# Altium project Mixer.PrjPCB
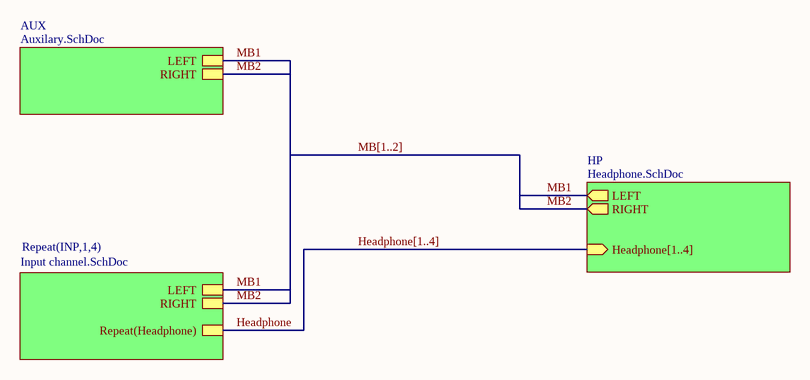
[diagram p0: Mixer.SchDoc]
4 sheets, 97 parts. Net scope: hierarchical (ports join the sheet entries above them; power ports are global).
Board file: Mixer.PCBDOC
Sheets:
  Mixer.SchDoc
    AUX = Auxilary.SchDoc
    HP = Headphone.SchDoc
    INP1 = Input channel.SchDoc
    INP2 = Input channel.SchDoc
    INP3 = Input channel.SchDoc
    INP4 = Input channel.SchDoc

## Sheet Mixer.SchDoc: Multi-Channel Design
size 431 x 279 mm; Organization: Altium Limited; Address1: L3, 12a Rodborough Rd; Address2: Frenchs Forest; Address3: NSW; Address4: Australia 2086; DocumentNumber: 5; SheetNumber: 5; SheetTotal: 8

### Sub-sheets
AUX = Auxilary.SchDoc: LEFT, RIGHT
HP = Headphone.SchDoc: Headphone[1..4] (in), LEFT (out), RIGHT (out)
Repeat(INP,1,4) = Input channel.SchDoc: LEFT, RIGHT, Repeat(Headphone)

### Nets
MB1: sheet AUX/LEFT, sheet HP/LEFT, sheet Repeat(INP,1,4)/LEFT  [project net LCHANNEL]
MB2: sheet AUX/RIGHT, sheet HP/RIGHT, sheet Repeat(INP,1,4)/RIGHT

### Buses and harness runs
bus Headphone[1..4] = sheet HP/Headphone[1..4]
bus MB[1..2]

## Sheet Auxilary.SchDoc: Multi-Channel Design
size 431 x 279 mm; Organization: Altium Limited; Address1: L3, 12a Rodborough Rd; Address2: Frenchs Forest; Address3: NSW; Address4: Australia 2086; DocumentNumber: 1; SheetNumber: 1; SheetTotal: 8
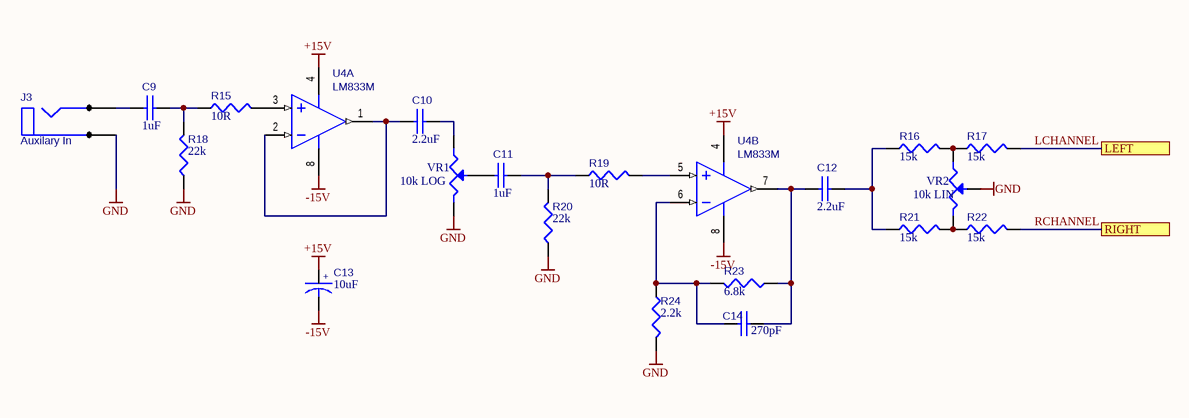
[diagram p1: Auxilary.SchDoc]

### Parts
C9  1uF  [RB.2/.4-NP]
C10  2.2uF  [RB.2/.4-NP]
C11  1uF  [RB.2/.4-NP]
C12  2.2uF  [RB.2/.4-NP]
C13  10uF  [RB.2/.4]
C14  270pF  [RAD0.2]
J3  Auxilary In  [JACK-6.25MM]
R15  10R  [AXIAL0.4]
R16  15k  [AXIAL0.4]
R17  15k  [AXIAL0.4]
R18  22k  [AXIAL0.4]
R19  10R  [AXIAL0.4]
R20  22k  [AXIAL0.4]
R21  15k  [AXIAL0.4]
R22  15k  [AXIAL0.4]
R23  6.8k  [AXIAL0.4]
R24  2.2k  [AXIAL0.4]
U4  LM833M  [DIP8]  (parts A,B of 2)
VR1  10k LOG  [POT - 24MM]
VR2  10k LIN  [POT - 24MM]

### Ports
LEFT, RIGHT

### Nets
+15V: C13.1 U4.4(V-)
-15V: C13.2 U4.8(V+)
GND: J3.3(C) R18.1 R20.1 R24.2 VR1.3 VR2.2(W)
LCHANNEL: R17.2 ; port LEFT
RCHANNEL: R22.2 ; port RIGHT  [project net MB2]
NetC9_1: C9.1 J3.1(A)
NetC9_2: C9.2 R15.1 R18.2
NetC10_1: C10.1 U4.1(OUT1) U4.2(IN1-)
NetC10_2: C10.2 VR1.1
NetC11_1: C11.1 VR1.2(W)
NetC11_2: C11.2 R19.1 R20.2
NetC12_1: C12.1 C14.2 R23.1 U4.7(OUT2)
NetC12_2: C12.2 R16.1 R21.1
NetC14_1: C14.1 R23.2 R24.1 U4.6(IN2-)
NetR15_2: R15.2 U4.3(IN1+)
NetR16_2: R16.2 R17.1 VR2.1
NetR19_2: R19.2 U4.5(IN2+)
NetR21_2: R21.2 R22.1 VR2.3

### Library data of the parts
C9-C12 C14 = CAP: Capacitor
C13 = CAPACITOR POL: Bi-Polar Capacitor
J3 = PHONEJACK MONO
R15-R24 = RES1: Resistor
U4 = LM833M: Fast Settling Dual Operational Amplifier
VR1 VR2 = POT1: Potentiometer

## Sheet Headphone.SchDoc: Multi-Channel Design
size 431 x 279 mm; Organization: Altium Limited; Address1: L3, 12a Rodborough Rd; Address2: Frenchs Forest; Address3: NSW; Address4: Australia 2086; DocumentNumber: 3; SheetNumber: 3; SheetTotal: 8
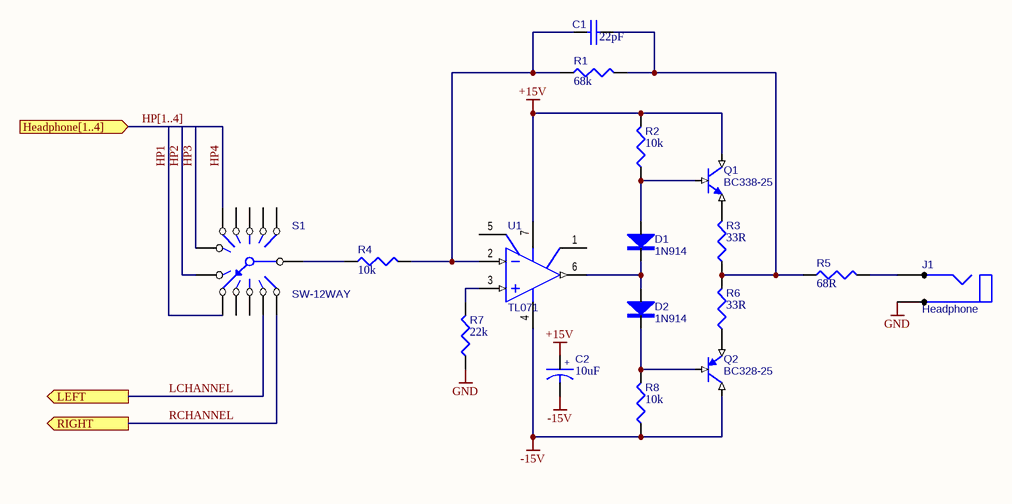
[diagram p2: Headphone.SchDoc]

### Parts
C1  22pF  [RAD0.2]
C2  10uF  [RB.2/.4]
D1  1N914  [DIODE0.4]
D2  1N914  [DIODE0.4]
J1  Headphone  [JACK-6.25MM]
Q1  BC338-25  [TO-92A]
Q2  BC328-25  [TO-92A]
R1  68k  [AXIAL0.4]
R2  10k  [AXIAL0.4]
R3  33R  [AXIAL0.4]
R4  10k  [AXIAL0.4]
R5  68R  [AXIAL0.4]
R6  33R  [AXIAL0.4]
R7  22k  [AXIAL0.4]
R8  10k  [AXIAL0.4]
S1  SW-12WAY  [SW-12WAY]
U1  TL071  [DIP8]

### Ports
Headphone[1..4] (in), LEFT (out), RIGHT (out)

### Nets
+15V: C2.1 Q1.1(C) R2.2 U1.7(VCC+)
-15V: C2.2 Q2.1(C) R8.1 U1.4(VCC-)
GND: J1.3(C) R7.1
HP1: S1.8  [project net Headphone1]
HP2: S1.7  [project net Headphone2]
HP3: S1.6  [project net Headphone3]
HP4: S1.5  [project net Headphone4]
LCHANNEL: S1.11 ; port LEFT
RCHANNEL: S1.12 ; port RIGHT  [project net MB2]
NetC1_1: C1.1 R1.1 R4.2 U1.2(IN-)
NetC1_2: C1.2 R1.2 R3.1 R5.1 R6.2
NetD1_1: D1.1(A) Q1.2(B) R2.1
NetD1_2: D1.2(K) D2.1(A) U1.6(OUT)
NetD2_2: D2.2(K) Q2.2(B) R8.2
NetJ1_1: J1.1(A) R5.2
NetQ1_3: Q1.3(E) R3.2
NetQ2_3: Q2.3(E) R6.1
NetR4_1: R4.1 S1.13
NetR7_2: R7.2 U1.3(IN+)

Not connected (* = marked no-connect by the designer): S1 1 2 3 4 9 10; U1 1(N1/O.S.) 5(O.S._N2)

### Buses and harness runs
bus HP[1..4] = port Headphone[1..4]

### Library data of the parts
C1 = CAP: Capacitor
C2 = CAPACITOR POL: Bi-Polar Capacitor
D1 D2 = 1N914: Diode
J1 = PHONEJACK MONO
Q1 = BC338-25: NPN BJT
Q2 = BC328-25: PNP BJT
R1-R8 = RES1: Resistor
U1 = TL071: Low-Noise  JFET-Input Operational Amplifiers

## Sheet Input channel.SchDoc: Multi-Channel Design
size 431 x 279 mm; Organization: Altium Limited; Address1: L3, 12a Rodborough Rd; Address2: Frenchs Forest; Address3: NSW; Address4: Australia 2086; DocumentNumber: 4; SheetNumber: 4; SheetTotal: 8
Used 4 times, as channels INP1, INP2, INP3, INP4. Parts and nets are listed once, with the designators drawn on the sheet.
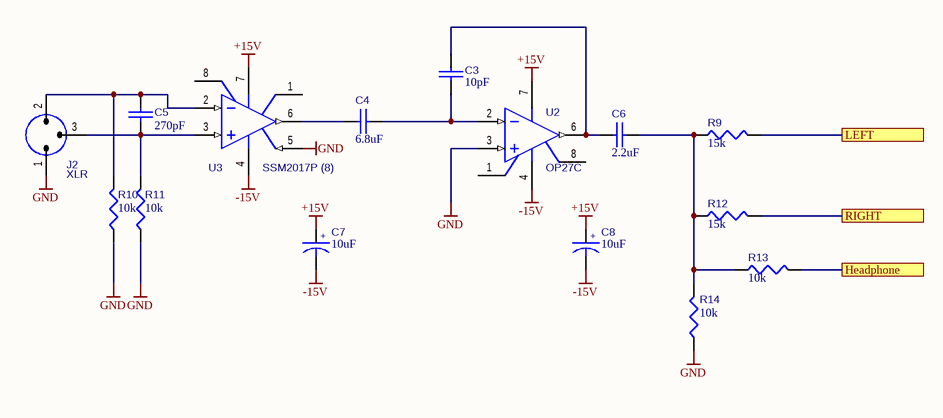
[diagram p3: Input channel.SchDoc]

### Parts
C3  10pF  [RAD0.2]
C4  6.8uF  [RB.2/.4-NP]
C5  270pF  [RAD0.2]
C6  2.2uF  [RB.2/.4-NP]
C7  10uF  [RB.2/.4]
C8  10uF  [RB.2/.4]
J2  XLR  [XLR-FEMALE]
R9  15k  [AXIAL0.4]
R10  10k  [AXIAL0.4]
R11  10k  [AXIAL0.4]
R12  15k  [AXIAL0.4]
R13  10k  [AXIAL0.4]
R14  10k  [AXIAL0.4]
U2  OP27C  [DIP8]
U3  SSM2017P (8)  [DIP8]

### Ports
Headphone, LEFT, RIGHT

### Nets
+15V: C7.1 C8.1 U2.7(V+) U3.7(V+)
-15V: C7.2 C8.2 U2.4(V-) U3.4(V-)
GND: J2.1 R10.1 R11.1 R14.1 U2.3(+IN) U3.5(REF)
Headphone: R13.2 ; port Headphone
LEFT: R9.2 ; port LEFT
RIGHT: R12.2 ; port RIGHT
NetC3_1: C3.1 C4.2 U2.2(-IN)
NetC3_2: C3.2 C6.1 U2.6(OUT)
NetC4_1: C4.1 U3.6(OUT)
NetC5_1: C5.1 J2.2 R10.2 U3.2(IN-)
NetC5_2: C5.2 J2.3 R11.2 U3.3(IN+)
NetC6_2: C6.2 R9.1 R12.1 R13.1 R14.2

Not connected (* = marked no-connect by the designer): U2 1(TRIM) 8(TRIM); U3 1(RG1) 8(RG2)

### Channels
INP1: designators C3=INP1_C3 C4=INP1_C4 C5=INP1_C5 C6=INP1_C6 C7=INP1_C7 C8=INP1_C8 J2=INP1_J2 R9=INP1_R9 R10=INP1_R10 R11=INP1_R11 R12=INP1_R12 R13=INP1_R13 R14=INP1_R14 U2=INP1_U2 U3=INP1_U3; ports Headphone=Headphone1 LEFT=LCHANNEL RIGHT=MB2
INP2: designators C3=INP2_C3 C4=INP2_C4 C5=INP2_C5 C6=INP2_C6 C7=INP2_C7 C8=INP2_C8 J2=INP2_J2 R9=INP2_R9 R10=INP2_R10 R11=INP2_R11 R12=INP2_R12 R13=INP2_R13 R14=INP2_R14 U2=INP2_U2 U3=INP2_U3; ports Headphone=Headphone2 LEFT=LCHANNEL RIGHT=MB2
INP3: designators C3=INP3_C3 C4=INP3_C4 C5=INP3_C5 C6=INP3_C6 C7=INP3_C7 C8=INP3_C8 J2=INP3_J2 R9=INP3_R9 R10=INP3_R10 R11=INP3_R11 R12=INP3_R12 R13=INP3_R13 R14=INP3_R14 U2=INP3_U2 U3=INP3_U3; ports Headphone=Headphone3 LEFT=LCHANNEL RIGHT=MB2
INP4: designators C3=INP4_C3 C4=INP4_C4 C5=INP4_C5 C6=INP4_C6 C7=INP4_C7 C8=INP4_C8 J2=INP4_J2 R9=INP4_R9 R10=INP4_R10 R11=INP4_R11 R12=INP4_R12 R13=INP4_R13 R14=INP4_R14 U2=INP4_U2 U3=INP4_U3; ports Headphone=Headphone4 LEFT=LCHANNEL RIGHT=MB2

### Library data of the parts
C3-C6 = CAP: Capacitor
C7 C8 = CAPACITOR POL: Bi-Polar Capacitor
J2 = XLR: XLR connector, PCB mounted
R9-R14 = RES1: Resistor
U2 = OP27C: Low Noise, High Speed Precision Operational Amplifier
U3 = SSM2017P (8): Self-Contained Audio Preamplifier

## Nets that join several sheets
+15V: Auxilary (C13.1 U4.4), Headphone (C2.1 Q1.1 R2.2 U1.7), INP1 (INP1_C7.1 INP1_C8.1 INP1_U2.7 INP1_U3.7), INP2 (INP2_C7.1 INP2_C8.1 INP2_U2.7 INP2_U3.7), INP3 (INP3_C7.1 INP3_C8.1 INP3_U2.7 INP3_U3.7), INP4 (INP4_C7.1 INP4_C8.1 INP4_U2.7 INP4_U3.7)
-15V: Auxilary (C13.2 U4.8), Headphone (C2.2 Q2.1 R8.1 U1.4), INP1 (INP1_C7.2 INP1_C8.2 INP1_U2.4 INP1_U3.4), INP2 (INP2_C7.2 INP2_C8.2 INP2_U2.4 INP2_U3.4), INP3 (INP3_C7.2 INP3_C8.2 INP3_U2.4 INP3_U3.4), INP4 (INP4_C7.2 INP4_C8.2 INP4_U2.4 INP4_U3.4)
GND: Auxilary (6 pins), Headphone (J1.3 R7.1), INP1 (6 pins), INP2 (6 pins), INP3 (6 pins), INP4 (6 pins)
Headphone1: Headphone (S1.8), INP1 (INP1_R13.2)
Headphone2: Headphone (S1.7), INP2 (INP2_R13.2)
Headphone3: Headphone (S1.6), INP3 (INP3_R13.2)
Headphone4: Headphone (S1.5), INP4 (INP4_R13.2)
LCHANNEL: Auxilary (R17.2), Headphone (S1.11), INP1 (INP1_R9.2), INP2 (INP2_R9.2), INP3 (INP3_R9.2), INP4 (INP4_R9.2)
MB2: Auxilary (R22.2), Headphone (S1.12), INP1 (INP1_R12.2), INP2 (INP2_R12.2), INP3 (INP3_R12.2), INP4 (INP4_R12.2)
